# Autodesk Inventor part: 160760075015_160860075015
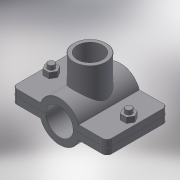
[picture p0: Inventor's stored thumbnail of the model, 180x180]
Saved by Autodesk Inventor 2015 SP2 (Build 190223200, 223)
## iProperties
Created: 2017-05
Part Number: 160760075015_160860075015
Material: Generic
Description: PLASSON SADDLE 75-1.1/2"
Document SubType Name: Modeling
Designer: KIM
Density: 1 g/cm^3
Appearance: Default
Author: KIM
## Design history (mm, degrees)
derived "16076.ipt"
feature "Solid1::16076.ipt"
feature "Solid2::16076.ipt"
tag "TaggingFeature1"
body "Solid1"
other parameters: "d0" = 93.75, "d1" = 122, "d2" = 37.5, "d3" = 75, "d4" = 98, "d5" = 0, "d6" = 6.1, "d7" = 122, "d8" = 0.1, "d10" = 0, "d11" = 0.75, "d14" = 58.2985, "d20" = 0.75, "d23" = 0.75, "d37" = 8, "d38" = 45.5, "d39" = 0, "d40" = 3, "d41" = 5, "d42" = 0, "d43" = 6, "d44" = 3, "d45" = 0, "d46" = 0.75, "d51" = 73, "d52" = 44.845, "d53" = 25, "d54" = 0, "d57" = 0, "d58" = 81, "d60" = 0, "d63" = 8, "d66" = 82, "d_" = 75, "G_" = 44.845, "A_" = 73, "L_" = 122, "L_1" = 98, "l_2" = 25
